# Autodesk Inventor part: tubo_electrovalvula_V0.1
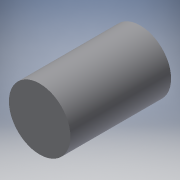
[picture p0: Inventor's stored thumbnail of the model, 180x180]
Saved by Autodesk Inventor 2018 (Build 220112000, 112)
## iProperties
Created: 2018-09
Part Number: tubo_electrovalvula_V0.1
Material: Generic
Document SubType Name: Modeling
Designer: Gordillo
Density: 1 g/cm^3
Appearance: Default
Author: Gordillo
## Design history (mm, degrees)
sketch "Sketch1"
  geometry: C1 r 55 at (0, 0); 1 further point
  constraints: 1 centre point, 1 coincident
  dimensions: "d0" = 110 diameter of C1
extrude "Extrusion1" new body sketch "Sketch1" distance "d1" = 180; taper "d2" = 0 deg
body "Solid1"
